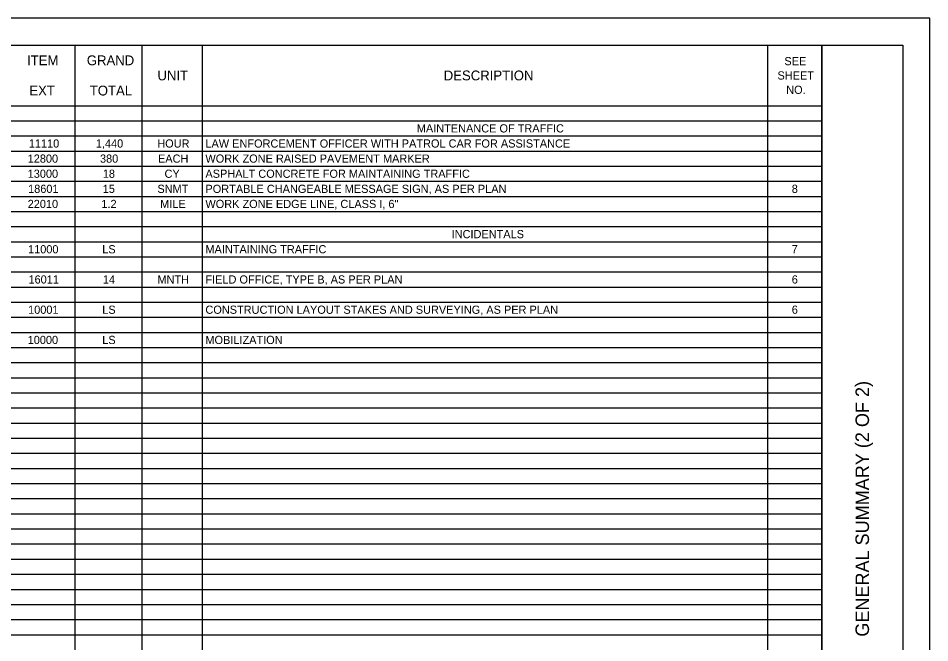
# Model space of a CAD drawing. Extents: x 0 to 34, y 0 to 22.
# Drawn here: x 17.12 to 34, y 10.43 to 22 of the extents above; entities that cross this region are included whole.
import ezdxf

# ---------------------------------------------------------------- set-up
doc = ezdxf.new("R2010")
doc.units = 0
for name, color, linetype in [('SH_Border', 7, 'Continuous'), ('SH_Cut_Line', 7, 'Continuous'), ('SH_Data', 7, 'Continuous'), ('SH_Text', 7, 'Continuous')]:
    doc.layers.add(name, color=color, linetype=linetype)

msp = doc.modelspace()

# ---------------------------------------------------------------- linework, layer by layer
at = {"layer": 'SH_Border'}
msp.add_line((32, 0.5), (32, 21.5), dxfattribs=at)
msp.add_lwpolyline([(1.5, 21.5), (33.5, 21.5), (33.5, 0.5), (1.5, 0.5)], close=True, dxfattribs=at)
at = {"layer": 'SH_Cut_Line'}
msp.add_lwpolyline([(0, 0), (34, 0), (34, 22), (0, 22)], close=True, dxfattribs=at)
at = {"layer": 'SH_Text'}
for p, q in [((1.5, 21.5), (32, 21.5)), ((18.173, 21.5), (18.173, 0.502)), ((19.409, 21.5), (19.409, 0.502)), ((20.53, 21.5), (20.53, 0.502)), ((30.994, 21.5), (30.994, 0.502)), ((32, 21.5), (32, 0.502)), ((1.5, 20.38), (32, 20.38)), ((1.5, 20.1), (32, 20.1)), ((1.5, 19.82), (32, 19.82)), ((1.5, 19.54), (32, 19.54)), ((1.5, 19.26), (32, 19.26)), ((1.5, 18.98), (32, 18.98)), ((1.5, 18.7), (32, 18.7)), ((1.5, 18.42), (32, 18.42)), ((1.5, 18.14), (32, 18.14)), ((1.5, 17.86), (32, 17.86)), ((1.5, 17.58), (32, 17.58)), ((1.5, 17.3), (32, 17.3)), ((1.5, 17.02), (32, 17.02)), ((1.5, 16.74), (32, 16.74)), ((1.5, 16.46), (32, 16.46)), ((1.5, 16.18), (32, 16.18)), ((1.5, 15.9), (32, 15.9)), ((1.5, 15.62), (32, 15.62)), ((1.5, 15.34), (32, 15.34)), ((1.5, 15.061), (32, 15.061)), ((1.5, 14.781), (32, 14.781)), ((1.5, 14.501), (32, 14.501)), ((1.5, 14.221), (32, 14.221)), ((1.5, 13.941), (32, 13.941)), ((1.5, 13.661), (32, 13.661)), ((1.5, 13.381), (32, 13.381)), ((1.5, 13.101), (32, 13.101)), ((1.5, 12.821), (32, 12.821)), ((1.5, 12.541), (32, 12.541)), ((1.5, 12.261), (32, 12.261)), ((1.5, 11.981), (32, 11.981)), ((1.5, 11.701), (32, 11.701)), ((1.5, 11.421), (32, 11.421)), ((1.5, 11.141), (32, 11.141)), ((1.5, 10.861), (32, 10.861)), ((1.5, 10.581), (32, 10.581))]:
    msp.add_line(p, q, dxfattribs=at)

# ---------------------------------------------------------------- texts
at = {"layer": 'SH_Data'}
msp.add_text('GENERAL SUMMARY (2 OF 2)', height=0.25, rotation=90, dxfattribs=at).set_placement((32.875, 10.544))
at = {"layer": 'SH_Text'}
for s, height, p in [('ITEM', 0.1818, (17.286, 21.129)), ('GRAND', 0.1818, (18.392, 21.129)), ('SEE ', 0.1515, (31.308, 21.129)), ('UNIT', 0.1818, (19.7, 20.849)), ('DESCRIPTION', 0.18182, (25.001, 20.849)), ('SHEET ', 0.1515, (31.18, 20.864)), ('EXT', 0.1818, (17.328, 20.569)), ('TOTAL', 0.1818, (18.447, 20.569)), ('NO.', 0.1515, (31.342, 20.599)), ('MAINTENANCE OF TRAFFIC', 0.15152, (24.502, 19.884)), ('11110', 0.1515, (17.318, 19.604)), ('1,440', 0.1515, (18.559, 19.604)), ('HOUR', 0.1515, (19.697, 19.604)), ('LAW ENFORCEMENT OFFICER WITH PATROL CAR FOR ASSISTANCE', 0.15152, (20.588, 19.604)), ('12800', 0.1515, (17.297, 19.324)), ('380', 0.1515, (18.636, 19.324)), ('EACH', 0.1515, (19.71, 19.324)), ('WORK ZONE RAISED PAVEMENT MARKER', 0.15152, (20.588, 19.324)), ('13000', 0.1515, (17.297, 19.044)), ('18', 0.1515, (18.688, 19.044)), ('CY', 0.1515, (19.831, 19.044)), ('ASPHALT CONCRETE FOR MAINTAINING TRAFFIC', 0.15152, (20.588, 19.044)), ('18601', 0.1515, (17.305, 18.764)), ('15', 0.1515, (18.687, 18.764)), ('SNMT', 0.1515, (19.699, 18.764)), ('PORTABLE CHANGEABLE MESSAGE SIGN, AS PER PLAN', 0.15152, (20.588, 18.764)), ('8', 0.152, (31.445, 18.764)), ('22010', 0.1515, (17.297, 18.484)), ('1.2', 0.1515, (18.662, 18.484)), ('MILE', 0.1515, (19.75, 18.484)), ('WORK ZONE EDGE LINE, CLASS I, 6"', 0.15152, (20.588, 18.484)), ('INCIDENTALS', 0.15152, (25.147, 17.925)), ('11000', 0.1515, (17.304, 17.645)), ('LS', 0.1515, (18.678, 17.645)), ('MAINTAINING TRAFFIC', 0.15152, (20.588, 17.645)), ('7', 0.152, (31.442, 17.645)), ('16011', 0.1515, (17.312, 17.085)), ('14', 0.1515, (18.689, 17.085)), ('MNTH', 0.1515, (19.7, 17.085)), ('FIELD OFFICE, TYPE B, AS PER PLAN', 0.15152, (20.588, 17.085)), ('6', 0.152, (31.445, 17.085)), ('10001', 0.1515, (17.305, 16.525)), ('LS', 0.1515, (18.678, 16.525)), ('CONSTRUCTION LAYOUT STAKES AND SURVEYING, AS PER PLAN', 0.15152, (20.588, 16.525)), ('6', 0.152, (31.445, 16.525)), ('10000', 0.1515, (17.297, 15.965)), ('LS', 0.1515, (18.678, 15.965)), ('MOBILIZATION', 0.15152, (20.588, 15.965))]:
    msp.add_text(s, height=height, dxfattribs=at).set_placement(p)

doc.saveas('drawing.dxf')
